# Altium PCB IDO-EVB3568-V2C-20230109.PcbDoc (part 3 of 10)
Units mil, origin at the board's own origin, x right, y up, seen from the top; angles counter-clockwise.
Board outline 5318 x 3544 mil, 2 copper layers (TOP, BOTTOM), stack 6.8 mil thick; 790 components, 626 nets, 2890 pads, 1922 vias.
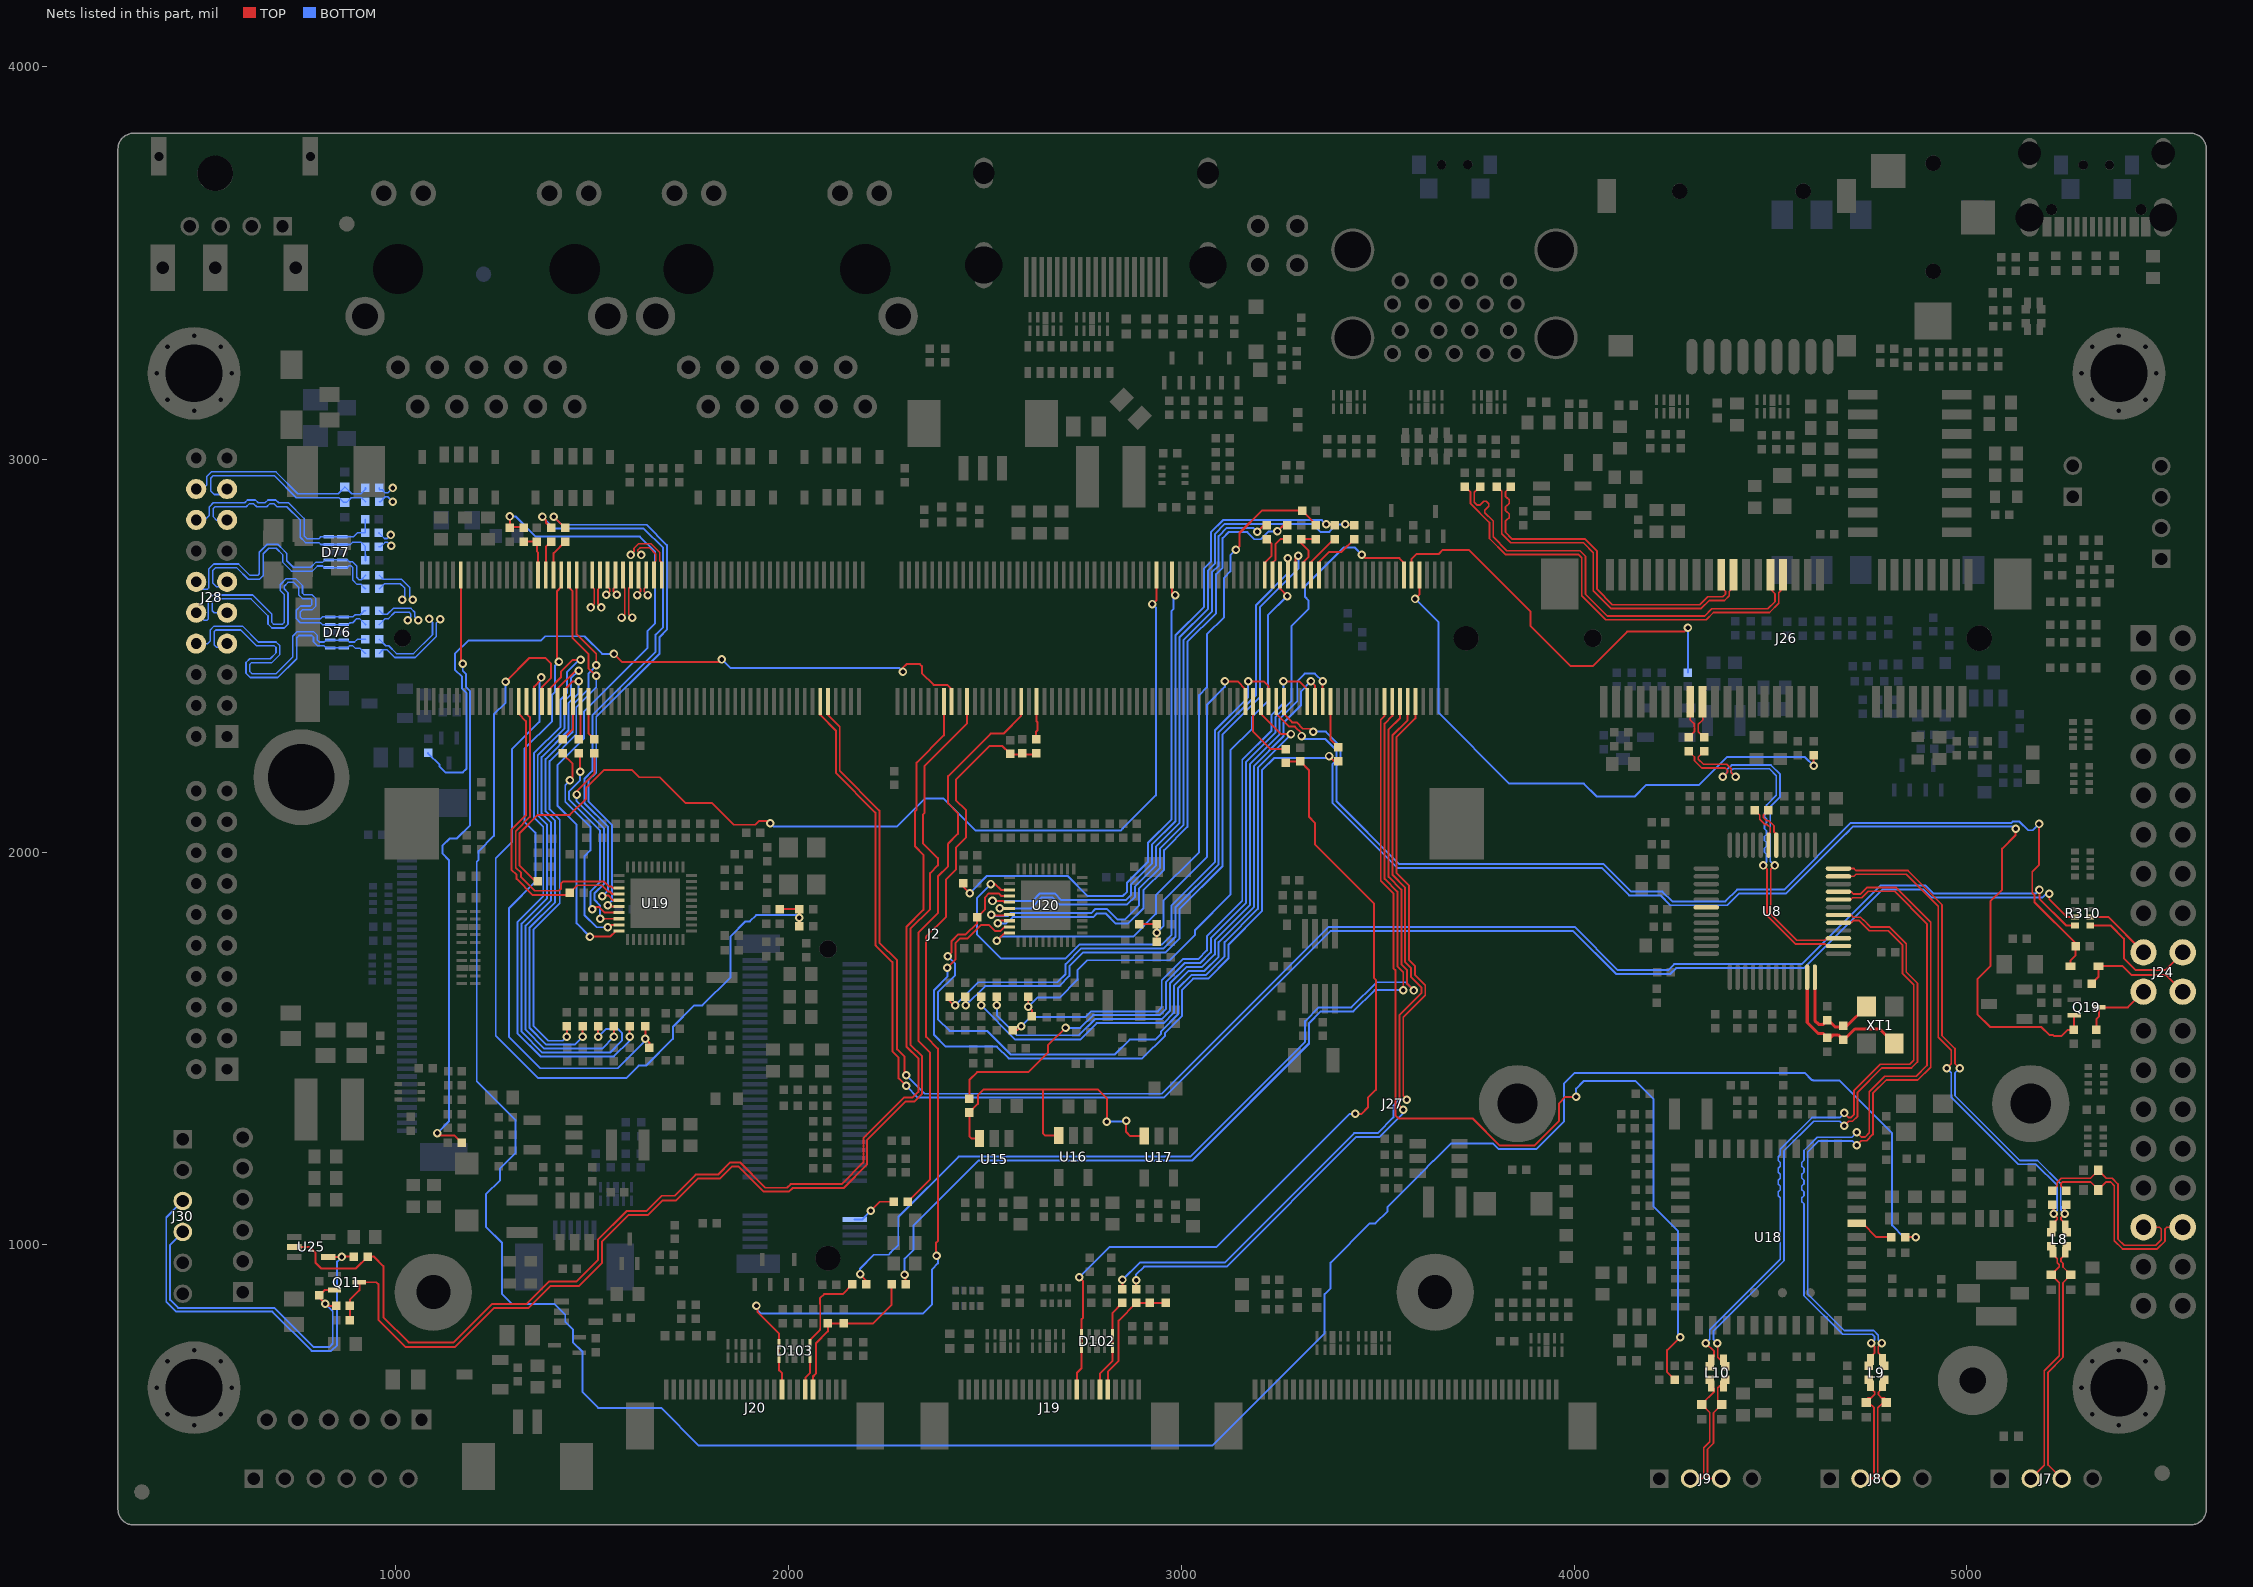
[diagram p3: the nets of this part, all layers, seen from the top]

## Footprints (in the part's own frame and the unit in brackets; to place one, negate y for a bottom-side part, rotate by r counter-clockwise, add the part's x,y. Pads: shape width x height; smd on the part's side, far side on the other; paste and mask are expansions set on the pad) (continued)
SILKSCREEN_TOP#34 [mm] "SILKSCREEN_TOP"
  rect 0.85x1.6 smd: 1(-1.25,0) 2(1.25,0)
  silkscreen extent -1.91,-1.04 1.88,1.09, body extent -1.8,-0.95 1.8,0.95, height 3.81

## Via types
v1: diameter 21.65, hole 11.81, TOP to BOTTOM, 1878 vias
v2: diameter 17.72, hole 7.87, TOP to BOTTOM, 44 vias

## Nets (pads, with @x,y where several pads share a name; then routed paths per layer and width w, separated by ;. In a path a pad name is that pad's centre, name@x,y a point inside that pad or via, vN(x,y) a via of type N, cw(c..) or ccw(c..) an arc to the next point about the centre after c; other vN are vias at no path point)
4G_PWREN_H_GPIO0_D5: J2.11 R344.1 | length 1053.2
  TOP w5: J2.11@3586.22,2706.42 3586.22,2747.22 3599,2760 3656,2760 3666,2770 3732,2770 3888.5,2613.5 3888.5,2576.5 3991,2474 4047,2474 4135,2562 4280,2562 v1(4290,2572)
  BOTTOM w5: R344.1@4290,2457.72 v1(4290,2572)
4G_RESET_L_GPIO0_D4: J2.9 R337.2 | length 1502.4
  TOP w5: v1(3595,2645) 3605.9,2655.9 J2.9@3605.9,2706.42 ; v1(4610,2220) R337.2@4610,2247.28
  BOTTOM w5: v1(3595,2645) 3595.9,2645 3655,2585.9 3655,2355 3835,2175 4025.14,2175 4058.14,2142 4154,2142 4183,2171 4318,2171 4389,2242 4588,2242 v1(4610,2220)
5G_SSRXN: J26.23 R423.2 | length 1131.6
  TOP w4.5: R423.2@3722,2931.28 3736.5,2916.78 3736.5,2887.5 3784.5,2839.5 3784.5,2799.06 3825.06,2758.5 4011.06,2758.5 4019.5,2750.06 4019.5,2653.06 4080.56,2592 4336.44,2592 4354.94,2610.5 4497.5,2610.5 4521.1,2634.1 4521.1,2661.1 4532.1,2672.1 J26.23@4532.1,2706.4
5G_SSRXP: J26.25 R422.2 | length 1135.8
  TOP w4.5: R422.2@3761,2931.28 3746,2916.28 3746,2891.44 3753.43,2884.01 3759.79,2884.01 3769.71,2893.93 3776.07,2893.93 3782.44,2887.56 3782.44,2881.2 3772.52,2871.28 3772.52,2864.92 3794,2843.44 3794,2803 3829,2768 4015,2768 4029,2754 4029,2657 4084.5,2601.5 4332.5,2601.5 4351,2620 4493.56,2620 4511.6,2638.03 4511.6,2658.4 4500.6,2669.4 J26.25@4500.6,2706.4
5G_SSTXN: C187.2 J26.31 | length 911.7
  TOP w4.5: C187.2@3803,2931.28 3815.5,2918.78 3815.5,2811.5 3839,2788 4024,2788 4049,2763 4049,2665.56 4093.56,2621 4324,2621 4344,2641 4383,2641 4395.1,2653.1 4395.1,2664.1 4406.1,2675.1 J26.31@4406.1,2706.4
5G_SSTXP: C189.2 J26.33 | length 899.7
  TOP w4.5: C189.2@3839,2931.28 3825,2917.28 3825,2906.26 3829.5,2901.76 3830.5,2901.76 3835,2897.26 3835,2888.26 3830.5,2883.76 3829.5,2883.76 3825,2879.26 3825,2870.26 3829.5,2865.76 3830.5,2865.76 3835,2861.26 3835,2852.26 3830.5,2847.76 3829.5,2847.76 3825,2843.26 3825,2815.44 3842.94,2797.5 4027.94,2797.5 4058.5,2766.94 4058.5,2669.5 4097.5,2630.5 4320.06,2630.5 4340.06,2650.5 4379.06,2650.5 4385.6,2657.03 4385.6,2664.4 4374.6,2675.4 J26.33@4374.6,2706.4
BT_REG_ON_H_GPIO1_D4: J2.18 R209.1 | length 2651.5
  TOP w5: J2.18@3517.32,2383.58 3517.32,2347.32 3507.63,2337.63 3507.63,1927.37 3540,1895 3540,1705 3545,1700 3545,1330 3553,1322 3742.14,1322 3811.14,1253 3898.72,1253 3961.83,1316.12 3961.83,1360.83 3978,1377 v1(4005,1377) ; R209.1@4256,657.28 4237,676.28 4237,732 v1(4270,765)
  BOTTOM w5: v1(4005,1377) 4005,1398 4024,1417 4157,1417 4201.67,1372.33 4201.67,1098.33 4265,1035 4265,770 v1(4270,765)
BT_WAKE_HOST: R199.2 U18.7 | length 102.5
  TOP w5: U18.7@4719.41,1055.43 4734.57,1055.43 4770,1020 R199.2@4807.28,1020
BT_WAKE_HOST_H_GPIO2_C1: J2.228 R199.1 | length 6682.9
  TOP w5: v1(1279,2434) 1340,2495 1380,2495 1395,2480 1395,2444 1371.65,2420.65 J2.228@1371.65,2383.58 ; R199.1@4842.72,1020 v1(4870,1020)
  BOTTOM w5: v1(1279,2434) 1279,2381 1249,2351 1249,2041.43 1210.5,2002.93 1210.5,1980.5 1205.67,1975.67 1205.67,1416.92 1304,1318.59 1304,1234 1265,1195 1265,1165 1229,1129 1229,1046 1270,1005 1270,875 1295,850 1402.86,850 1431,821.86 1431,804.21 1450.33,784.88 1450.33,752.1 1475,727.43 1475,625 1515,585 1675,585 1771,489 3079,489 3365,775 3365,875 3380,890 3380,955 3480,1055 3485.86,1055 3494.14,1055 3525.14,1086 3525.14,1097 3610.67,1182.53 3610.67,1183.09 3641.91,1214.32 3642.47,1214.32 3686.14,1258 3793.95,1258 3807.88,1244.07 3816.16,1244.07 ; 3816.16,1244.08 3904.07,1244.08 3974,1314 3974,1410 4002,1438 4587,1438 4605,1420 4607.86,1420 4608.86,1419 4675,1419 4810,1284 4810,1050 4840,1020 v1(4870,1020)
CAM0_PDN_H_GPIO1_D0: J2.10 R150.1 | length 2045.9
  TOP w5: R150.1@2850,887.72 v1(2850,911) ; v1(3574,1370) 3574,1371 3565,1380 3565,1580 3621,1636 3621,1661 3595,1687 3595,1710 3580,1725 3580,1915 3547.63,1947.37 3547.63,2292.63 3596.06,2341.06 J2.10@3596.06,2383.58
  BOTTOM w5: v1(2850,911) 2894,955 3110,955 3440,1285 3500,1285 3540,1325 3540,1355 3555,1370 v1(3574,1370)
CAM0_RST_L__GPIO1_D1: J2.12 R151.1 | length 2009.5
  TOP w5: R151.1@2885,887.72 v1(2885,910) ; v1(3565,1344) 3555,1354 3555,1585 3611,1641 3611,1656 3585,1682 3585,1705 3570,1720 3570,1910 3537.63,1942.37 3537.63,2297.63 3576.37,2336.37 J2.12@3576.37,2383.58
  BOTTOM w5: v1(2885,910) 2885,925 2905,945 3115,945 3445,1275 3505,1275 3565,1335 v1(3565,1344)
CAM1_PDN_H_GPIO1_D2: J2.14 R164.1 | length 2613.7
  TOP w5: v1(2182,925.88) 2182,924 2197.72,908.28 R164.1@2197.72,900 ; J2.14@3556.69,2383.58 3556.69,2341.69 3527.63,2312.63 3527.63,1937.37 3560,1905 3560,1715 3575,1700 3575,1665 v1(3592,1648)
  BOTTOM w5: v1(2182,925.88) 2182,940 2217,975 2254.25,975 2260.11,980.86 2279,999.75 2279,1071.14 2432.86,1225 2975.57,1225 3017,1225 3022,1225 3315,1518 3315,1570 3350,1605 3433,1605 3497,1669 3571,1669 v1(3592,1648)
CAM1_RST_L_GPIO1_C7: J2.16 R165.1 | length 2448.5
  TOP w5: v1(2295,924) 2297.72,921.28 R165.1@2297.72,900 ; J2.16@3537,2383.58 3537,2347 3517.63,2327.63 3517.63,1932.37 3550,1900 3550,1710 3565,1695 v1(3565,1649)
  BOTTOM w5: v1(2295,924) 2295,965 2318,988 2318,1050 2483,1215 2971.43,1215 3021.14,1215 3027,1215 3325,1513 3325,1565 3355,1595 3438,1595 3492,1649 v1(3565,1649)
CAM_CLKOUT0: J2.108 R163.1 | length 97.7
  TOP w5: R163.1@2630,2287.72 2630,2307.05 2633,2310.05 2633,2332 2631.49,2333.51 J2.108@2631.49,2383.58
CAMERA_PWREN: R416.2 U15.3 U16.3 U17.3 | length 828.4
  TOP w5: U15.3@2486.17,1271.37 2465,1271.37 2460,1276.37 R416.2@2460,1337.28 2482,1359.28 2482,1381 2497,1396 2648,1396 ; U16.3@2687.6,1278.15 2653,1278.15 2648,1283.15 2648,1396 ; v1(2810,1314) 2810,1373 2787,1396 2648,1396 ; v1(2859.37,1316.16) 2859.37,1287.63 2869.91,1277.09 U17.3@2905.32,1277.09
  BOTTOM w5: v1(2810,1314) 2857.21,1314 v1(2859.37,1316.16)
CAMERA_PWREN_GPIO4_D2: J2.13 R416.1 | length 2226.9
  TOP w5: R416.1@2460,1372.72 2460,1420 2480,1440 2610,1440 2660,1490 2660,1508 v1(2705,1553) ; v1(3459,2758) 3468,2749 3555,2749 3566.53,2737.47 J2.13@3566.53,2706.42
  BOTTOM w5: v1(2705,1553) 2743,1553 2775,1585 2945,1585 2961,1601 2961,1670 3009,1718 3048,1718 3075,1745 3075,1781 3165,1871 3165,2230 3240,2305 3240,2345 3280,2385 3280,2576 3324,2620 3324,2641 3315,2650 3315,2678 3413,2776 3441,2776 v1(3459,2758)
CAN1_RX: J24.18 R310.5 | length 330.3
  TOP w5: R310.5@5314.69,1813.5 5366.5,1813.5 5400,1780 5400,1730 5430,1700 5505,1700 J24.18@5550,1745
CAN1_RX_M0: J2.154 R310.4 | length 4402.7
  TOP w5: J2.154@2100,2383.58 2100,2350 2130,2320 2130,2207 2231,2106 2231,1770 2276,1725 2276,1498 2295,1479 2295,1436 v1(2299,1432) ; v1(5185,1904) 5185,1882.15 5253.64,1813.5 R310.4@5275.31,1813.5
  BOTTOM w5: v1(2299,1432) 2346,1385 2950,1385 3375,1810 4001.14,1810 4111.14,1700 4240,1700 4255,1715 4580,1715 4780,1915 4895,1915 4915,1895 5176,1895 v1(5185,1904)
CAN1_TX: J24.17 R310.6 | length 172.7
  TOP w5: R310.6@5314.69,1835.16 5359.84,1835.16 J24.17@5450,1745
CAN1_TX_M0: J2.156 R310.3 | length 4413.7
  TOP w5: J2.156@2080.31,2383.58 2080.31,2349.69 2120,2310 2120,2202 2221,2101 2221,1762 2222,1762 2264,1720 2264,1493 2280,1477 2280,1424 v1(2299,1405) ; v1(5210,1894) 5210,1880 5254.84,1835.16 R310.3@5275.31,1835.16
  BOTTOM w5: v1(2299,1405) 2329,1375 2955,1375 3380,1800 3997,1800 4107,1690 4245,1690 4260,1705 4585,1705 4785,1905 4890,1905 4910,1885 5193,1885 5202,1894 v1(5210,1894)
CAN2_RX: D90.C J24.20 R401.2 | length 293.8
  TOP w5: R401.2@5317.72,1665 5335.43,1682.71 D90.C@5335.43,1710 5397,1710 5420,1687 5508,1687 J24.20@5550,1645
CAN2_RX_M0: D90.A J2.44 R398.2 | length 2768.5
  TOP w5: J2.44@3261.41,2383.58 3261.41,2351.59 3282.2,2330.8 3293.2,2330.8 3309.5,2314.5 3328.5,2314.5 v1(3336,2307) ; v1(5184,2072) 5184,1967.92 5166.67,1950.59 5166.67,1896.41 5173,1890.08 5173,1872 5277.28,1767.72 R398.2@5277.28,1760 5277.28,1737.28 5264.57,1724.57 D90.A@5264.57,1710
  BOTTOM w5: v1(3336,2307) 3368,2307 3405,2270 3405,2230 3395,2220 3395,2130 3555,1970 4075,1970 4145,1900 4225,1900 4250,1875 4330.43,1875 4385,1875 4415,1905 4535,1905 4705,2075 5010.28,2075 5114.08,2075 5117.41,2078.33 5132.59,2078.33 ; 5132.6,2078.32 5133.68,2078.32 5156,2056 5168,2056 v1(5184,2072)
CAN2_TX: J24.19 Q19.3 R400.2 | length 190
  TOP w5: R400.2@5330,1547.72 5330,1575 5336.5,1581.5 Q19.3@5336.5,1605 5410,1605 J24.19@5450,1645
CAN2_TX_M0: J2.46 Q19.2 R399.2 | length 3124.4
  TOP w5: J2.46@3241.73,2383.58 3241.73,2353.27 3275,2320 3289,2320 3306,2303 v1(3306,2296) ; v1(5125,2060) 5124,2059 5124,2043 5090,2009 5090,1905 5060,1875 5060,1710 5027,1677 5027,1588 5060,1555 5190,1555 5209.99,1535.01 5218.79,1535.01 5222.13,1531.67 5240.63,1531.67 5256.67,1547.72 R399.2@5273,1547.72 5273.5,1548.22 Q19.2@5273.5,1585.32
  BOTTOM w5: v1(3306,2296) 3314,2288 3367,2288 3395,2260 3395,2235 3385,2225 3385,2125 3550,1960 4070,1960 4140,1890 4220,1890 4245,1865 4326.28,1865 4390,1865 4420,1895 4540,1895 4686.57,2041.57 4692.43,2047.43 4710,2065 5058.51,2065 5108.22,2065 5120,2065 v1(5125,2060)
CIF_CLK0: C95.2 D102.5 D102.6 J19.9 R149.2 | length 2218.5
  TOP w5: J19.9@2733.9,632.01 2733.9,673.9 2745.63,685.63 D102.6@2745.63,737.78 D102.5@2745.63,772.22 2745.63,810.63 2750,815 2750,908 v1(2740,918) ; R149.2@3266,2227.28 3270,2231.28 C95.2@3303,2231.28 3325,2209.28 3325,2090 3340,2075 3340,2020 3490,1870 3490,1680 3495,1675 3495,1395 3475,1375 3475,1350 3459,1334 v1(3443,1334)
  BOTTOM w5: v1(2740,918) 2817,995 3090,995 3429,1334 v1(3443,1334)
CIF_CLK1: C97.2 D103.5 D103.6 J20.9 R163.2 R421.2 | length 2373.4
  TOP w5: v1(1918,845) 1920,843 1920,830 1975.63,774.37 D103.5@1975.63,747.22 D103.6@1975.63,712.78 1975.63,680.37 1983.19,672.81 J20.9@1983.19,632.01 ; v1(2376.5,972.5) 2375,974 2375,1005 2380,1010 2380,1500 2350,1530 2350,1784.14 2350.81,1784.96 2350.81,1785.81 2400,1835 2400,1930 2425.95,1955.95 2425.95,1970.95 2426,1971 2426,2012 2451,2037 2451,2107.64 2426,2132.64 2426,2185.14 2511.97,2271.12 2543.16,2271.12 C97.2@2564,2250.28 2565,2249.28 2592,2249.28 R421.2@2595,2252.28 2598,2249.28 2627,2249.28 R163.2@2630,2252.28
  BOTTOM w5: v1(1918,845) 1920,843 1920,835 1930,825 2341,825 2365,849 2365,938 2380,953 2380,969 v1(2376.5,972.5)
CIF_CLKOUT_SOC: J2.52 R149.1 | length 178.1
  TOP w5: J2.52@3182.67,2383.58 3182.67,2307.33 3227.28,2262.72 R149.1@3266,2262.72
CIF_PDN0: D102.1 D102.10 J19.6 R150.2 | length 243.9
  TOP w5: J19.6@2792.95,632.01 2792.95,672.95 2824.37,704.37 D102.10@2824.37,737.78 D102.1@2824.37,772.22 2824.37,826.65 R150.2@2850,852.28
CIF_PDN1: D103.1 D103.10 J20.6 R164.2 | length 345.7
  TOP w5: J20.6@2042.24,632.01 2042.24,662.25 2054.37,674.37 D103.10@2054.37,712.78 D103.1@2054.37,747.22 2054.37,758.37 2080,784 2080,786.02 2080.33,786.35 2080.33,849.65 2080,849.98 2080,865 2090,875 2137.28,875 R164.2@2162.28,900
CIF_RST0: C96.2 J19.5 R151.2 R156.1 | length 325.2
  TOP w5: J19.5@2812.64,632.01 2812.64,677.64 2840,705 2840,807.28 R151.2@2885,852.28 C96.2@2920,852.28 R156.1@2960,852.28
CIF_RST1: C99.2 J20.5 R165.2 R166.1 | length 418.5
  TOP w5: J20.5@2061.93,632.01 2061.93,665 2069,672.07 2069,749 2100,780 C99.2@2100,800.28 R166.1@2140,800.28 2215.28,800.28 2262.28,847.28 R165.2@2262.28,900
CLK_32K_OUT: J27.68 R352.2 | length 118.1
  TOP w5: v1(2209,1087) 2232,1110 R352.2@2267.28,1110
  BOTTOM w5: J27.68@2167.91,1064.72 2186.72,1064.72 v1(2209,1087)
CLK_32K_OUT_GPIO0_B0: J2.112 R352.1 | length 1458.3
  TOP w5: R352.1@2302.72,1110 2360,1167.28 2360,1490 2330,1520 2330,1795 2380,1845 2380,1938.29 2405.95,1964.24 2405.95,1979.24 2406,1979.29 2406,2021 2406.33,2021.33 2406.33,2022.26 2431,2046.94 2431,2099.35 2406,2124.35 2406,2194 2514,2302 2547,2302 2592.12,2347.12 J2.112@2592.12,2383.58
DM1_: D18.2 J7.2 L8.3 R52.2 | length 647.8
  TOP w4.5: J7.2@5163.03,405 5197.5,439.47 5197.5,679.94 5235.5,717.94 5235.5,903.4 D18.2@5215,923.9 5235.5,944.4 5235.5,949.5 5230.25,954.75 5230.25,964.75 5219.25,975.75 L8.3@5219.25,981.53 5219.25,993.03 R52.2@5215,997.28
DM2_: D23.2 J8.2 L9.3 R64.2 | length 315.4
  TOP w4.5: J8.2@4729.33,405 4759.45,405 4763.95,409.5 4763.95,585 4750.05,598.9 D23.2@4744,598.9 4744,605.5 4748.5,610 4755.25,610 4765.56,620.31 4765.56,624.44 4754.25,635.75 L9.3@4754.25,641.53 4754.25,653.03 R64.2@4750,657.28
DM3_: D25.2 J9.2 L10.3 R75.2 | length 317.9
  TOP w4.5: J9.2@4295.63,405 4325.75,405 4330.25,409.5 4330.25,483.69 4345.5,498.94 4345.5,573.4 D25.2@4325,593.9 4325,595 4356.5,626.5 4356.5,633.44 4351,638.94 4350.05,638.94 4349.25,639.74 L10.3@4349.25,640.53 4346.74,640.53 4345,642.28 R75.2@4345,656.28
DM4: J26.36 R340.1 | length 101.5
  TOP w4.5: J26.36@4327.4,2383.6 4327.4,2336.67 4316.4,2325.67 4316.4,2307.32 R340.1@4331,2292.72
DM_1: D65.1 J24.31 R307.2 | length 545.9
  TOP w4.5: R307.2@5217,1137.72 5230.25,1150.97 5230.25,1159.94 5240.31,1170 5315,1170 5334.9,1189.9 D65.1@5334.9,1190 5354.9,1170 5369.94,1170 5385,1154.94 5385,1015 5400.5,999.5 5481.06,999.5 5495.25,1013.69 5495.25,1040.5 5490.75,1045 J24.31@5450,1045
DP1_: D20.2 J7.3 L8.4 R56.2 | length 647.5
  TOP w4.5: J7.3@5241.77,405 5207,439.77 5207,676 5245,714 5245,903.9 D20.2@5265,923.9 5245,943.9 5245,953.44 5239.75,958.69 5239.75,964.75 5250.75,975.75 L8.4@5250.75,981.53 5250.75,993.03 R56.2@5255,997.28
DP2_: D22.2 J8.3 L9.4 R67.2 | length 316.1
  TOP w4.5: R67.2@4790,657.28 4785.75,653.03 L9.4@4785.75,641.53 4785.75,635.75 4775.06,625.06 4775.06,618.69 4783.75,610 4790.5,610 4795,605.5 D22.2@4795,598.9 4787.35,598.9 4773.45,585 4773.45,409.5 4777.95,405 J8.3@4808.07,405
DP3_: D26.2 J9.3 L10.4 R78.2 | length 316.3
  TOP w4.5: J9.3@4374.37,405 4344.25,405 4339.75,409.5 4339.75,479.75 4355,495 4355,572.9 D26.2@4376,593.9 4366,603.9 4366,636 4370.53,640.53 L10.4@4380.75,640.53 4380.75,652.03 R78.2@4385,656.28
DP4: J26.38 R341.1 | length 101.6
  TOP w4.5: R341.1@4292,2292.72 4306.9,2307.62 4306.9,2325.67 4295.9,2336.67 J26.38@4295.9,2383.6
DP_1: D64.1 J24.32 R308.2 | length 546.6
  TOP w4.5: R308.2@5253,1137.72 5239.75,1150.97 5239.75,1156 5244.25,1160.5 5315,1160.5 5334.9,1140.6 D64.1@5334.9,1140 5355.4,1160.5 5366,1160.5 5375.5,1151 5375.5,1011.06 5396.56,990 5485,990 5504.75,1009.75 5504.75,1040.5 5509.25,1045 J24.32@5550,1045
DRV: U8.42
EDP_EN_H_GPIO0_C5: J2.130 R393.2 | length 1838.1
  TOP w5: v1(1555,2505) 1575,2485 1824,2485 v1(1830,2491) ; v1(2291,2460) 2291,2470 2300,2479 2334,2479 2339,2474 2339,2456 2369,2426 2404,2426 2414.96,2415.04 J2.130@2414.96,2383.58
  BOTTOM w5: R393.2@1082,2253.28 1082,2251.28 1111,2222.28 1111,2218 1125.73,2203.27 1170.27,2203.27 1179,2212 1179,2406.09 1168.67,2416.42 1168.67,2446.33 1150,2465 1150,2505 1184,2539 1369,2539 1380,2550 1480,2550 1525,2505 v1(1555,2505) ; v1(1830,2491) 1852,2469 2282,2469 v1(2291,2460)
EDP_ON_: J30.4 Q11.2 R388.2 R389.2 | length 864.6
  TOP w5: Q11.2@843.5,885.32 818.03,885.32 R388.2@805,872.28 805,865 v1(820,850) 825,845 R389.2@847.28,845
  BOTTOM w5: J30.4@457.09,1033.27 457.09,1032.09 425,1000 425,860 445,840 690,840 790,740 830,740 839,749 839,831 v1(820,850)
EDP_ON_GPIO0_C3: J2.126 Q11.3 R387.2 R389.1 | length 3152.5
  TOP w5: R387.2@882.72,808 R389.1@882.72,845 882.72,860.72 906.5,884.5 Q11.3@906.5,905 950,905 955,900 955,810 1025,740 1150,740 1250,840 1338,840 1393,895 1465,895 1525,955 1525,990.71 1525,1007.28 1525,1009 1592,1076 1633.29,1076 1641.57,1076 1679.28,1113.71 1713.71,1113.71 1769,1169 1825,1169 1856,1200 1871.86,1200 1936.19,1135.66 2000.66,1135.66 2010,1145 2140,1145 2200,1205 2200,1267.71 2297.29,1365 2320,1365 2340,1385 2340,1480 2310,1510 2310,1805 2360,1855 2360,1946.75 2379.65,1966.41 2379.65,1985.2 2341.67,2023.18 2341.67,2095.74 2346,2100.06 2346,2220.14 2454.33,2328.47 J2.126@2454.33,2383.58
EDP_PWM7: J2.132 R390.1 U25.2 | length 3253.2
  TOP w5: U25.2@740.53,995 780,995 795,980 795,955 810,940 897.72,940 R390.1@927.72,970 944,970 968,946 968,816 1032,752 1147,752 1245,850 1333,850 1390,907 1460,907 1514,961 1514,1013 1587,1086 1637.43,1086 1676.72,1125.29 1709.29,1125.29 1763,1179 1820,1179 1851,1210 1876,1210 1940.34,1145.66 1995.66,1145.66 2005,1155 2135,1155 2190,1210 2190,1271.86 2293.14,1375 2315,1375 2330,1390 2330,1475 2300,1505 2300,1810 2343,1853 2343,1993.57 2321.67,2014.9 2321.67,2104.02 2326,2108.35 2326,2228.43 2395.27,2297.7 J2.132@2395.27,2383.58
EDP_PWM7_: J30.3 R390.2 U25.4 | length 1062.2
  TOP w5: U25.4@827.14,969.41 v1(862,969.41) 862.59,970 R390.2@892.28,970
  BOTTOM w5: J30.3@457.09,1112.01 415,1069.92 415,855 440,830 685,830 785,730 835,730 850,745 850,957.41 v1(862,969.41)
EDP_TX_AUXN: C235.2 J2.197 | length 198.1
  TOP w4: v1(1598,2757) 1606,2765 1606,2774 1617.6,2785.6 1649.4,2785.6 1671.77,2763.23 1671.77,2742.23 1676.77,2737.23 J2.197@1676.77,2706.42
  BOTTOM w4: C235.2@956.72,2778 960.72,2778 971.72,2789 979,2789 v1(987.65,2780.36)
EDP_TX_AUXN_: C235.1 D77.4 D77.7 J28.15 R384.2 | length 569.7
  BOTTOM w4: J28.15@570,2846.18 568.82,2845 543.86,2845 535,2853.86 535,2875.77 539,2879.77 618.77,2879.77 626,2887 638,2887 645.22,2879.77 670.77,2879.77 678,2887 690,2887 697.22,2879.77 722.09,2879.77 756,2845.86 756,2801.86 769.33,2788.53 803.72,2788.53 808.56,2783.68 D77.4@828.78,2783.68 D77.7@863.22,2783.68 884,2783.68 889.32,2789 912,2789 921.28,2779.72 C235.1@921.28,2778 921.28,2758.17 922.28,2757.17 R384.2@922.28,2743
EDP_TX_AUXP: C236.2 J2.199 | length 167
  TOP w4: v1(1625,2757) 1616,2766 1616,2769.86 1621.74,2775.6 1645.26,2775.6 1661.77,2759.08 1661.77,2741.77 1657.08,2737.08 J2.199@1657.08,2706.42
  BOTTOM w4: C236.2@956.72,2814 956.72,2813 970.72,2799 978,2799 v1(987,2808)
EDP_TX_AUXP_: C236.1 D77.5 D77.6 J28.16 R385.1 | length 576.9
  BOTTOM w4: J28.16@491.26,2846.18 513.18,2846.18 525,2858 525,2879.91 534.86,2889.77 614.62,2889.77 621.85,2897 642.14,2897 649.37,2889.77 666.62,2889.77 673.85,2897 694.14,2897 701.37,2889.77 726.23,2889.77 766,2850 766,2806 773.48,2798.53 803.72,2798.53 808.57,2803.37 D77.5@828.78,2803.37 D77.6@863.22,2803.37 891.82,2803.37 902.45,2814 C236.1@921.28,2814 R385.1@921.28,2848
EDP_TX_D0N: C241.2 J2.213 | length 315.3
  TOP w4: J2.213@1519.29,2706.42 1519.29,2674.29 1514.45,2669.45 1514.45,2654.14 1514.44,2632 v1(1523.09,2623.35)
  BOTTOM w4: C241.2@957.72,2507 966.24,2515.52 977.34,2515.52 996.86,2496 1049,2496 1103,2550 1103,2583.71 v1(1112.65,2593.36)
EDP_TX_D0N_: C241.1 D76.1 D76.10 J28.7 | length 792.4
  BOTTOM w4: J28.7@570,2531.22 560.78,2522 543,2522 537,2528 537,2562 541,2566 604.86,2566 645.38,2525.47 690.53,2525.47 694.53,2521.47 694.53,2507.67 679.86,2493 627.86,2493 618,2483.14 618,2455.86 628.86,2445 699.14,2445 747,2492.86 747,2546 752.86,2551.86 786,2551.86 790,2547.86 790,2536 800.53,2525.47 817.53,2525.47 822.37,2520.63 D76.1@832.78,2520.63 D76.10@867.22,2520.63 876.63,2520.63 881.47,2525.47 890.38,2525.47 896.86,2519 909,2519 921,2507 C241.1@922.28,2507
EDP_TX_D0P: C242.2 J2.215 | length 302
  TOP w4: v1(1495.8,2623.35) 1504.44,2632 1504.44,2658.28 1504.45,2670.55 1499.6,2675.4 J2.215@1499.6,2706.42
  BOTTOM w4: C242.2@957.72,2542 974.2,2525.52 981.49,2525.52 1001,2506 1044.86,2506 1093,2554.14 1093,2586 v1(1085,2594)
EDP_TX_D0P_: C242.1 D76.2 D76.9 J28.8 | length 793.3
  BOTTOM w4: J28.8@491.26,2531.22 520.22,2531.22 527,2538 527,2566.14 536.86,2576 609,2576 649.53,2535.47 694.67,2535.47 704.53,2525.62 704.53,2503.53 684,2483 632,2483 628,2479 628,2460 633,2455 695,2455 737,2497 737,2550.14 748.71,2561.86 790.14,2561.86 800,2552 800,2540.14 804.67,2535.47 817.47,2535.47 822.32,2540.32 D76.2@832.78,2540.32 D76.9@867.22,2540.32 876.68,2540.32 881.53,2535.47 894.52,2535.47 901.05,2542 C242.1@922.28,2542
EDP_TX_D1N: C239.2 J2.209 | length 170.7
  TOP w4: J2.209@1558.66,2706.42 1558.66,2676.66 1553.82,2671.82 1553.82,2664 v1(1562.46,2655.36)
  BOTTOM w4: C239.2@957.72,2580 972.72,2595 981,2595 997,2611 1034,2611 1038,2607 1038,2599 v1(1030,2591)
EDP_TX_D1N_: C239.1 D76.4 D76.7 J28.9 | length 784.3
  BOTTOM w4: J28.9@570,2609.96 537.04,2609.96 532,2615 532,2638 539,2645 630.86,2645 674,2601.86 674,2581 684,2571 715.14,2571 725,2580.86 725,2661 715.14,2670.86 715.14,2677.14 725,2687 739.86,2687 752,2674.86 752,2655.86 761.86,2646 782,2646 786,2642 786,2631.14 781.86,2627 757,2627 746,2616 746,2595 756.48,2584.53 807.72,2584.53 812.56,2579.68 D76.4@832.78,2579.68 D76.7@867.22,2579.68 878.68,2579.68 883.52,2584.53 889.67,2584.53 900.14,2595 907.28,2595 C239.1@922.28,2580
EDP_TX_D1P: C240.2 J2.211 | length 184.8
  TOP w4: v1(1535.17,2655.36) 1543.82,2664 1543.82,2671.18 1538.97,2676.03 J2.211@1538.97,2706.42
  BOTTOM w4: C240.2@957.72,2615 966.65,2606.07 977.93,2606.07 992.86,2621 1038.14,2621 1048,2611.14 1048,2600 v1(1057,2591)
EDP_TX_D1P_: C240.1 D76.5 D76.6 J28.10 | length 815.4
  BOTTOM w4: J28.10@491.26,2609.96 510.05,2591.17 519.17,2591.17 522,2594 522,2642.14 534.86,2655 635,2655 684,2606 684,2585.14 688.14,2581 711,2581 715,2585 715,2656.86 705.14,2666.71 705.14,2681.29 720.86,2697 744,2697 762,2679 762,2660 766,2656 786.14,2656 796,2646.14 796,2627 786,2617 761.14,2617 756,2611.86 756,2599.14 760.62,2594.53 807.72,2594.53 812.57,2599.37 D76.5@832.78,2599.37 D76.6@867.22,2599.37 890.37,2599.37 896,2605 909,2605 919,2615 C240.1@922.28,2615
EDP_TX_D2N: C237.2 J2.205 | length 221.3
  TOP w4: J2.205@1598.03,2706.42 1598.03,2677.03 1593,2672 1593,2606.29 v1(1601.65,2597.64)
  BOTTOM w4: C237.2@957.72,2671 970.72,2684 1011,2684 1022,2673 1022,2652 1015.76,2645.76 v1(1015.76,2643)
EDP_TX_D2N_: C237.1 D77.1 D77.10 J28.11 | length 633.5
  BOTTOM w4: J28.11@570,2688.7 557.47,2676.17 542.83,2676.17 533,2686 533,2717 540,2724 595,2724 624,2695 652.14,2695 662,2704.86 662,2759.86 676.14,2774 694.86,2774 712,2756.86 712,2738 734,2716 787.14,2716 800.14,2729 813,2729 817.37,2724.63 D77.1@828.78,2724.63 D77.10@863.22,2724.63 875.63,2724.63 880.47,2729.47 885.38,2729.47 890,2724.86 890,2693 901,2682 911,2682 922,2671 C237.1@922.28,2671
EDP_TX_D2P: C238.2 J2.207 | length 238.8
  TOP w4: v1(1574.36,2597.64) 1583,2606.28 1583,2672 1578.34,2676.66 J2.207@1578.34,2706.42
  BOTTOM w4: C238.2@957.72,2705 967.72,2695 1014.14,2695 1035,2674.14 1035,2651.05 v1(1043.05,2643)
EDP_TX_D2P_: C238.1 D77.2 D77.9 J28.12 | length 655.3
  BOTTOM w4: J28.12@491.26,2688.7 509.79,2670.17 520.17,2670.17 523,2673 523,2721.14 535.86,2734 599.14,2734 628.14,2705 648,2705 652,2709 652,2764 672,2784 690.71,2784 699,2784 716.14,2766.86 722,2761 722,2742.14 738.14,2726 783,2726 796,2739 814.01,2739 819.33,2744.32 D77.2@828.78,2744.32 D77.9@863.22,2744.32 876.68,2744.32 881.53,2739.47 889.53,2739.47 900,2729 900,2700 906,2694 911.28,2694 C238.1@922.28,2705
EDP_TX_D3N: C233.2 J2.201 | length 102.1
  TOP w4: J2.201@1637.4,2706.42 1637.4,2676.4 1632.56,2671.56 1632.56,2663.65 v1(1641.2,2655)
  BOTTOM w4: C233.2@957.72,2893 958.72,2892 959.72,2892 972.72,2905 979.09,2905 v1(991.74,2892.36)
EDP_TX_D3N_: C233.1 D80.1 J28.17 | length 517.9
  BOTTOM w4: J28.17@570,2924.92 556.08,2911 537,2911 528,2920 528,2952.51 534,2958.51 690.35,2958.51 745.86,2903 855,2903 867.1,2890.9 D80.1@870,2890.9 873.9,2890.9 886,2903 912.28,2903 C233.1@922.28,2893
EDP_TX_D3P: C234.2 J2.203 | length 104
  TOP w4: v1(1613.91,2655) 1622.56,2663.64 1622.56,2671.44 1617.71,2676.29 J2.203@1617.71,2706.42
  BOTTOM w4: C234.2@957.72,2928 957.72,2924 958.72,2923 964.72,2923 972.72,2915 979.09,2915 v1(991.74,2927.65)
EDP_TX_D3P_: C234.1 D79.1 J28.18 | length 507.2
  BOTTOM w4: J28.18@491.26,2924.92 491.34,2925 508,2925 518,2935 518,2956.66 529.86,2968.51 694.49,2968.51 750,2913 853,2913 870,2930 D79.1@870,2930.1 887.1,2913 910.71,2913 922.28,2924.57 C234.1@922.28,2928
EXT_EN: J2.249 R13.1 | length 1563.9
  TOP w5: v1(1105,1285) 1111,1279 1148.72,1279 R13.1@1167.72,1260 ; J2.249@1164.96,2706.42 1164.96,2486.04 1170,2481 v1(1170,2480)
  BOTTOM w5: v1(1105,1285) 1135,1315 1135,1933.29 1135,1980 1118,1997 1118,2016 1137,2035 1155,2035 1189,2069 1189,2410.24 1178.67,2420.57 1178.67,2445.42 1178.67,2453.33 1170,2462 v1(1170,2480)
FE1_1_DM0: R71.1 U8.30 | length 111.2
  TOP w4.5: R71.1@4495,2107.28 4482,2094.28 4482,2088.44 4490.44,2080 4496,2080 4509,2067 4509,2051.8 4514.8,2046 U8.30@4514.8,2018.3
FE1_1_DM1: L8.2 R52.1 R307.1 U8.23 | length 1320.2
  TOP w4.5: U8.23@4673.3,1938.6 4712.73,1938.6 4717.83,1943.7 4846.3,1943.7 4927.5,1862.5 4927.5,1529.06 4960.5,1496.07 4960.5,1461.68 v1(4948.82,1450) ; R52.1@5215,1032.72 5219.25,1036.97 L8.2@5219.25,1048.46 5219.25,1054.25 5230.25,1065.25 5230.25,1070 5230,1070 v1(5221,1079) 5221,1098.28 R307.1@5217,1102.28
  BOTTOM w4.5: v1(4948.82,1450) 4960.5,1438.32 4960.5,1376.07 5131.06,1205.5 5176.06,1205.5 5230,1151.56 5230,1094.86 5230.25,1094.61 5230.25,1088.25 v1(5221,1079)
FE1_1_DM2: L9.2 R64.1 U8.20 | length 1800.6
  TOP w4.5: U8.20@4673.3,1879.5 4704.5,1879.5 4709,1884 4732.44,1884 4748.94,1900.5 4816.06,1900.5 4898.5,1818.06 4898.5,1456.94 4871.06,1429.5 4791.06,1429.5 4751.5,1389.94 4751.5,1285.5 4741,1275 4731.68,1275 v1(4720,1286.68) ; R64.1@4750,692.72 4754.25,696.97 L9.2@4754.25,708.47 4754.25,714.25 4765.25,725.25 4765.25,741.5 v1(4756.57,750.18)
  BOTTOM w4.5: v1(4720,1286.68) 4707.82,1274.5 4619.5,1274.5 4585.5,1240.5 4585.5,1215.5 4580,1210 4580,1200.5 4585.5,1195 4585.5,1185.5 4580,1180 4580,1170.5 4585.5,1165 4585.5,1155.5 4580,1150 4580,1140.5 4585.5,1135 4585.5,1125.5 4580,1120 4580,1110.5 4585.5,1105 4585.5,871.06 4683.83,772.73 4758.83,772.73 4765.25,766.32 4765.25,758.87 v1(4756.57,750.18)
FE1_1_DM3: L10.2 R75.1 U8.17 | length 1635.9
  TOP w4.5: v1(4335.57,750) 4356.5,729.07 4356.5,716.8 4349.25,709.55 L10.2@4349.25,707.47 4349.25,695.97 R75.1@4345,691.72 ; U8.17@4673.3,1820.5 4705.5,1820.5 4711,1826 4725.7,1826 4751.7,1800 4800,1800 4836.5,1763.5 4836.5,1691 4865,1662.5 4865,1470 4855,1460 4780,1460 4712.5,1392.5 4712.5,1331.94 4704.96,1324.39 4699.39,1324.39 v1(4687.71,1336.08)
  BOTTOM w4.5: v1(4335.57,750) 4345.25,759.68 4345.25,783.69 4525,963.44 4525,1120 4520,1125 4520,1135 4525,1140 4525,1150 4520,1155 4520,1165 4525,1170 4525,1180 4520,1185 4520,1195 4525,1200 4525,1210 4520,1215 4520,1225 4525,1230 4525,1243.43 4605.96,1324.39 4676.03,1324.39 v1(4687.71,1336.08)
FE1_1_DM4: R340.2 U8.14 | length 895.4
  TOP w4.5: R340.2@4331,2257.28 4316.25,2242.53 4316.25,2237.19 4329.44,2224 4389,2224 4400.07,2212.93 4400.07,2202.93 v1(4411.18,2191.82) ; v1(4481.82,1966.31) 4491.5,1956.63 4491.5,1838.5 4563.5,1766.5 4638.5,1766.5 4643.6,1761.4 U8.14@4673.3,1761.4
  BOTTOM w4.5: v1(4411.18,2191.82) 4399.5,2203.5 4399.5,2207 4405,2212.5 4497.5,2212.5 4515,2195 4515,2145 4490,2120 4490,2105 4485,2100 4485,2090 4490,2085 4490,2075 4485,2070 4485,2060 4490,2055 4490,2045 4485,2040 4485,2030 4490,2025 4490,2015 4485,2010 4485,2000 4490,1995 4490,1974.49 v1(4481.82,1966.31)
FE1_1_DP0: R69.1 U8.31 | length 110.4
  TOP w4.5: R69.1@4460,2107.28 4472.5,2094.78 4472.5,2084.5 4486.5,2070.5 4492.06,2070.5 4499.5,2063.06 4499.5,2051.25 4495.2,2046.95 U8.31@4495.2,2018.3
FE1_1_DP1: L8.1 R56.1 R308.1 U8.24 | length 1335.8
  TOP w4.5: U8.24@4673.3,1958.3 4712.73,1958.3 4717.83,1953.2 4850.24,1953.2 4937,1866.44 4937,1533 4970,1500 4970,1461.68 v1(4981.68,1450) ; R308.1@5253,1102.28 5249,1098.28 v1(5249,1079) 5239.75,1069.75 5239.75,1065.25 5250.75,1054.25 L8.1@5250.75,1048.46 5250.75,1036.97 R56.1@5255,1032.72
  BOTTOM w4.5: v1(4981.68,1450) 4970,1438.32 4970,1380 5135,1215 5180,1215 5239.5,1155.5 5239.5,1098.8 5239.75,1098.55 5239.75,1088.25 v1(5249,1079)
FE1_1_DP2: L9.1 R67.1 U8.21 | length 1798.2
  TOP w4.5: U8.21@4673.3,1899.2 4705.8,1899.2 4711.5,1893.5 4728.5,1893.5 4745,1910 4820,1910 4908,1822 4908,1453 4875,1420 4795,1420 4761,1386 4761,1281.56 4744.94,1265.5 4731.68,1265.5 v1(4720,1253.82) ; v1(4783.43,750.18) 4774.75,741.5 4774.75,725.25 4785.75,714.25 L9.1@4785.75,708.47 4785.75,696.97 R67.1@4790,692.72
  BOTTOM w4.5: v1(4720,1253.82) 4708.82,1265 4623.44,1265 4595,1236.56 4595,875 4687.77,782.23 4762.77,782.23 4774.75,770.25 4774.75,758.87 v1(4783.43,750.18)
FE1_1_DP3: L10.1 R78.1 U8.18 | length 1634.6
  TOP w4.5: v1(4364.43,750) 4366,748.43 4366,714 4372.54,707.47 L10.1@4380.75,707.47 4380.75,695.97 R78.1@4385,691.72 ; U8.18@4673.3,1840.2 4705.36,1840.2 4711.06,1834.5 4729.22,1834.5 4736.15,1827.57 4737.56,1827.57 4755.63,1809.5 4803.94,1809.5 4846,1767.44 4846,1694.94 4874.5,1666.44 4874.5,1466.06 4858.94,1450.5 4783.94,1450.5 4722,1388.56 4722,1328 4708.89,1314.89 4699.39,1314.89 v1(4687.71,1303.21)
  BOTTOM w4.5: v1(4364.43,750) 4354.75,759.68 4354.75,779.75 4534.5,959.5 4534.5,1239.5 4609.89,1314.89 4676.02,1314.89 v1(4687.71,1303.21)
FE1_1_DP4: R341.2 U8.15 | length 896.3
  TOP w4.5: R341.2@4292,2257.28 4306.75,2242.53 4306.75,2233.25 4325.5,2214.5 4385.06,2214.5 4390.57,2209 4390.57,2204.07 v1(4378.32,2191.82) ; v1(4510.68,1966.31) 4501,1956.63 4501,1842.44 4567.44,1776 4638,1776 4643.1,1781.1 U8.15@4673.3,1781.1
  BOTTOM w4.5: v1(4378.32,2191.82) 4390,2203.5 4390,2210.94 4401.06,2222 4501.44,2222 4524.5,2198.94 4524.5,2141.06 4499.5,2116.06 4499.5,1977.5 v1(4510.68,1966.31)
FE1_1_XIN: C49.2 R68.1 U8.12 XT1.1 | length 278.9
  TOP w8: U8.12@4613.3,1681.7 4613.3,1571.29 4623,1561.59 4634.31,1561.59 C49.2@4645,1572.28 4647.72,1572.28 4665,1555 4682.28,1555 R68.1@4685,1557.72 4695.04,1557.72 XT1.1@4744.57,1607.24
FE1_1_XOUT: C51.2 R68.2 U8.11 XT1.3 | length 388.3
  TOP w8: U8.11@4593.6,1681.7 4593.6,1566.4 4621.19,1538.81 4633.91,1538.81 C51.2@4645,1527.72 4652.72,1527.72 4660,1535 4672.28,1535 R68.2@4685,1522.28 4687.28,1522.28 4715,1550 4778.19,1550 XT1.3@4815.43,1512.76
GMAC0_MCLKINOUT: C131.2 J2.230 R216.1 R219.2 | length 2192.8
  TOP w5: J2.230@1351.96,2383.58 1351.96,2421.96 1370,2440 v1(1370,2445) ; R216.1@1977.72,1855 R219.2@2027.28,1855 v1(2027.28,1833) C131.2@2027.28,1812
  BOTTOM w5: v1(1370,2445) 1365,2440 1365,2332 1296,2263 1296,2039.29 1296,2027 1254,1985 1254,1533.14 1266.58,1520.57 1266.58,1520.42 1362,1425 1586.36,1425 1618.03,1456.67 1636.67,1456.67 1705,1525 1705,1555 1760,1610 1780,1610 1852,1682 1852,1786 1890,1824 1901,1824 1917,1840 2020.28,1840 v1(2027.28,1833)
GMAC0_MDC: J2.232 U19.13 | length 758.9
  TOP w5: J2.232@1332.28,2383.58 1332.28,2352.72 1341,2344 1341,2089.86 1305,2053.86 1305,1961 1318.5,1947.5 1318.5,1936.5 1353,1902 1415,1902 1420,1907 1420,1920 1426,1926 1529,1926 1542,1913 1548.37,1913 1552,1909.37 U19.13@1567.48,1909.37
GMAC0_MDIO: J2.234 R249.1 U19.14 | length 777
  TOP w5: J2.234@1312.59,2383.58 1312.59,2352.41 1331,2334 1331,2094 1294,2057 1294,1955.92 1307,1942.92 1307,1932 1348,1891 1436.28,1891 R249.1@1442.28,1897 1461.28,1916 1524,1916 1540,1900 1545,1900 1551.38,1893.62 U19.14@1567.48,1893.62
GMAC0_RSTN_GPIO2_D5: J2.77 R248.1 | length 2587.7
  TOP w5: R248.1@1361.28,1926 1355,1926 1315,1966 1315,2049 1361,2095 1443,2095 1483.5,2135.5 1483.5,2163.5 1530,2210 1600,2210 1619,2191 1672,2191 1738,2125 1805,2125 1860,2070 1915,2070 1924,2079 1948,2079 v1(1953,2074) ; v1(2926,2632) 2928,2634 2929,2634 2936.61,2641.61 J2.77@2936.61,2706.42
  BOTTOM w5: v1(1953,2074) 1961,2066 1972.78,2066 1973.78,2065 2275.71,2065 2347.71,2137 2394,2137 2476,2055 2845.14,2055 2851,2060.86 2935,2144.86 2935,2623 v1(2926,2632)
GMAC0_RXCLK: C147.2 J2.223 R256.2 | length 1732.2
  TOP w5: v1(1415,2485) 1410,2490 1410,2665 1420.86,2675.86 J2.223@1420.86,2706.42 ; R256.2@1635,1557.28 v1(1635,1525) 1645,1515 C147.2@1645,1502.72
  BOTTOM w5: v1(1415,2485) 1405,2475 1405,2409.14 1397.5,2401.64 1397.5,2333.5 1327,2263 1327,2078 1355,2050 1355,1925 1288,1858 1288,1529 1367,1450 1565,1450 1635,1520 v1(1635,1525)
GMAC0_RXD0: J2.222 R252.2 | length 1321.8
  TOP w5: J2.222@1430.7,2383.58 1430.7,2415.7 1450,2435 v1(1465,2435) ; v1(1555,1530) R252.2@1555,1557.28
  BOTTOM w5: v1(1465,2435) 1465,2405 1439,2379 1439,2310 1371,2242 1371,2099 1395,2075 1395,1878 1330,1813 1330,1548 1378,1500 1525,1500 v1(1555,1530)
GMAC0_RXD1: J2.224 R253.2 | length 1514.9
  TOP w5: J2.224@1411.02,2383.58 1411.02,2416.02 1457.5,2462.5 v1(1465.5,2462.5) ; v1(1515,1530) R253.2@1515,1557.28
  BOTTOM w5: v1(1465.5,2462.5) 1445.5,2442.5 1445.5,2400.5 1429,2384 1429,2315 1361,2247 1361,2094 1385,2070 1385,1883 1320,1818 1320,1543 1373,1490 1545,1490 1575,1520 1575,1540 1565,1550 1535,1550 v1(1515,1530)
GMAC0_RXD2: J2.219 R254.2 | length 1452.7
  TOP w5: J2.219@1460.23,2706.42 1460.23,2554.77 1510,2505 v1(1510,2476) ; v1(1475,1530) R254.2@1475,1557.28
  BOTTOM w5: v1(1475,1530) 1455,1510 1383,1510 1340,1553 1340,1808 1405,1873 1405,2080 1381,2104 1381,2237 1449,2305 1449,2374 1490,2415 1490,2455 1510,2475 v1(1510,2476)
GMAC0_RXD3: J2.221 R255.2 | length 1397.2
  TOP w5: v1(1435,1530) R255.2@1435,1557.28 ; J2.221@1440.55,2706.42 1440.55,2674.45 1450,2665 1450,2545 1490,2505 1490,2469 v1(1510,2449)
  BOTTOM w5: v1(1435,1530) 1425,1520 1388,1520 1350,1558 1350,1803 1417,1870 1417,2083 1391,2109 1391,2232 1459,2300 1459,2369 1510,2420 v1(1510,2449)
GMAC0_RXDV_CRS: J2.226 R257.2 | length 1553.5
  TOP w5: J2.226@1391.33,2383.58 1391.33,2416.33 1420,2445 1420,2460 1450,2490 v1(1470,2490) ; v1(1595,1530) R257.2@1595,1557.28
  BOTTOM w5: v1(1470,2490) 1467,2490 1435,2458 1435,2405 1419,2389 1419,2320 1351,2252 1351,2089 1375,2065 1375,1888 1310,1823 1310,1538 1368,1480 1555,1480 1595,1520 v1(1595,1530)
GMAC0_TXCLK: C134.2 J2.229 R234.1 | length 120
  TOP w5: R234.1@1325,2791.28 C134.2@1359,2791.28 1359,2766 1361.81,2763.19 J2.229@1361.81,2706.42
GMAC0_TXCLK_: C135.2 R234.2 U19.20 | length 1668.2
  TOP w5: v1(1290,2855) C135.2@1290,2826.72 1291,2827.72 1324,2827.72 R234.2@1325,2826.72 ; v1(1494,1785) 1545,1785 1559.13,1799.13 U19.20@1567.48,1799.13
  BOTTOM w5: v1(1290,2855) 1305,2855 1356,2804 1621,2804 1660,2765 1660,2583 1641,2564 1641,2521 1479,2359 1479,2290 1411,2222 1411,2119 1460,2070 1460,1819 v1(1494,1785)
GMAC0_TXD0: J2.216 R224.1 | length 102.2
  TOP w5: J2.216@1489.76,2383.58 1489.76,2302.96 R224.1@1505,2287.72
GMAC0_TXD0_: R224.2 U19.18 | length 532.9
  TOP w5: v1(1460,2147) 1460,2155 1505,2200 R224.2@1505,2252.28 ; v1(1520,1830.63) U19.18@1567.48,1830.63
  BOTTOM w5: v1(1460,2147) 1460,2130 1530,2060 1530,1920 1505.5,1895.5 1505.5,1878.5 1520,1864 v1(1520,1830.63)
GMAC0_TXD1: J2.218 R227.1 | length 98
  TOP w5: R227.1@1465,2287.72 1470.07,2292.79 J2.218@1470.07,2383.58
GMAC0_TXD1_: R227.2 U19.17 | length 530.9
  TOP w5: R227.2@1465,2252.28 1469,2248.28 v1(1469,2205) ; v1(1500,1855) 1505,1860 1518,1860 1531.62,1846.38 U19.17@1567.48,1846.38
  BOTTOM w5: v1(1469,2205) 1469,2183 1441,2155 1441,2134 1520,2055 1520,1925 1495,1900 1495,1860 v1(1500,1855)
GMAC0_TXD2: J2.225 R228.1 | length 97.2
  TOP w5: J2.225@1401.18,2706.42 1401.18,2761.46 R228.1@1431,2791.28
GMAC0_TXD2_: R228.2 U19.16 | length 1417
  TOP w5: v1(1402,2854) 1429.28,2826.72 R228.2@1431,2826.72 ; v1(1539,1865) 1541,1865 1543.87,1862.13 U19.16@1567.48,1862.13
  BOTTOM w5: v1(1402,2854) 1422,2834 1638,2834 1690,2782 1690,2567 1671,2548 1671,2506 1510,2345 1510,2202.86 1490,2182.86 1490,2130 1550,2070 1550,1876 v1(1539,1865)
GMAC0_TXD3: J2.227 R231.1 | length 90.5
  TOP w5: J2.227@1381.49,2706.42 1381.49,2777.77 R231.1@1395,2791.28
GMAC0_TXD3_: R231.2 U19.15 | length 1425.3
  TOP w5: v1(1373,2854) 1382,2845 1382,2839.72 R231.2@1395,2826.72 ; v1(1525,1888) 1527,1890 1540,1890 1552.13,1877.87 U19.15@1567.48,1877.87
  BOTTOM w5: v1(1373,2854) 1403,2824 1630.85,2824 1680,2774.85 1680,2573 1661,2554 1661,2510.14 1500,2349.14 1500,2207 1480,2187 1480,2125 1540,2065 1540,1903 v1(1525,1888)
GMAC0_TXEN: J2.220 R232.1 | length 106.4
  TOP w5: R232.1@1425,2287.72 1450.39,2313.11 J2.220@1450.39,2383.58
GMAC0_TXEN_: R232.2 U19.19 | length 566
  TOP w5: R232.2@1425,2252.28 1425,2250 1450,2225 1450,2190 v1(1443,2183) ; v1(1539,1809) 1544.88,1814.88 U19.19@1567.48,1814.88
  BOTTOM w5: v1(1443,2183) 1431,2171 1431,2129 1495,2065 1495,2005 1480,1990 1480,1840 1511,1809 v1(1539,1809)
GMAC1_MCLKINOUT_M1: C155.2 J2.54 R270.1 R271.2 | length 893.2
  TOP w5: R270.1@2892.72,1817 C155.2@2937.28,1817 v1(2937.28,1795) R271.2@2937.28,1772 ; v1(3111,2435) 3143,2435 3162.99,2415.01 J2.54@3162.99,2383.58
  BOTTOM w5: v1(2937.28,1795) 2955,1812.72 2955,1877.79 3065,1987.79 3065,2375 3111,2421 v1(3111,2435)
GMAC1_MDC_M1: J2.48 U20.13 | length 1563.9
  TOP w5: v1(2515,1919) 2526,1919 2540.63,1904.37 U20.13@2562.48,1904.37 ; v1(3170,2435) 3210,2435 3222.04,2422.96 J2.48@3222.04,2383.58
  BOTTOM w5: v1(2515,1919) 2480,1884 2480,1790 2540,1730 2705,1730 2740,1765 2950,1765 2975,1790 2975,1865 3085,1975 3085,2310 3170,2395 v1(3170,2435)
GMAC1_MDIO_M1: J2.50 R297.1 U20.14 | length 2133.5
  TOP w5: v1(2405,1735) 2415,1745 2415,1774 2431,1790 2450,1790 2479.72,1819.72 R297.1@2479.72,1835 2500,1855.28 2500,1885 2510,1895 2535,1895 2541.38,1888.62 U20.14@2562.48,1888.62 ; J2.50@3202.36,2383.58 3202.36,2352.64 3254,2301 v1(3279,2301)
  BOTTOM w5: v1(2405,1735) 2423,1717 2423,1686 2380,1643 2380,1575 2410,1545 2505,1545 2565,1485 2830,1485 2868,1523 2933.92,1523 2948.33,1537.41 2948.33,1544.18 2991,1586.86 2991,1653 3026,1688 3063,1688 3110,1735 3110,1771 3195,1856 3195,2215 3279,2299 v1(3279,2301)
GMAC1_RSTN_GPIO2_D7: J2.73 R296.1 | length 1339.7
  TOP w5: R296.1@2444.28,1921 2444.28,1912.72 v1(2461,1896) ; J2.73@2975.98,2706.42 2975.98,2660 2980.98,2655 v1(2983.98,2655)
  BOTTOM w5: v1(2461,1896) 2505,1940 2710,1940 2762,1888 2850,1888 2862,1900 2862,1923 2915,1976 2915,2024 2975,2084 2975,2615 2979.98,2619.98 2979.98,2651 v1(2983.98,2655)
GMAC1_RXCLK_M1: C171.2 J2.45 R304.2 | length 1589.7
  TOP w5: R304.2@2610,1632.28 v1(2610,1607) 2619,1598 C171.2@2619,1582.72 ; J2.45@3251.57,2706.42 3251.57,2670.43 v1(3269.5,2652.5)
  BOTTOM w5: v1(2610,1607) 2633,1630 2690,1630 2735,1675 2735,1700 2760,1725 2970,1725 3035,1790 3035,1802 3125,1892 3125,2260 3180,2315 3180,2345 3220,2385 3220,2603 v1(3269.5,2652.5)
GMAC1_RXD0_M1: J2.34 R300.2 | length 1665.3
  TOP w5: v1(2530,1610) R300.2@2530,1632.28 ; J2.34@3359.84,2383.58 3359.84,2434.84 v1(3360,2435)
  BOTTOM w5: v1(2530,1610) 2530,1585 2581,1534 2739,1534 2780,1575 2950,1575 2971,1596 2971,1665.86 3013.14,1708 3053,1708 3085,1740 3085,1776 3175,1866 3175,2225 3250,2300 3250,2340 3295,2385 3295,2436 3314,2455 3340,2455 v1(3360,2435)
GMAC1_RXD1_M1: J2.36 R301.2 | length 1645.1
  TOP w5: v1(2490,1610) R301.2@2490,1632.28 ; v1(3330,2435) 3340.15,2424.85 J2.36@3340.15,2383.58
  BOTTOM w5: v1(2490,1610) 2577.07,1522.93 2742.07,1522.93 2784.14,1565 2955,1565 2981,1591 2981,1660 3019,1698 3058.86,1698 3095,1734.14 3095,1771 3185,1861 3185,2220 3260,2295 3260,2330 3305,2375 3305,2410 v1(3330,2435)
GMAC1_RXD2_M1: J2.41 R302.2 | length 1805
  TOP w5: R302.2@2450,1632.28 2451,1631.28 v1(2451,1610) ; J2.41@3290.94,2706.42 3290.94,2750 3295.94,2755 v1(3298,2755)
  BOTTOM w5: v1(2451,1610) 2500,1659 2689,1659 2715,1685 2715,1710 2750,1745 2960,1745 2995,1780 2995,1855 3105,1965 3105,2300 3200,2395 3200,2624 3298,2722 v1(3298,2755)
GMAC1_RXD3_M1: J2.43 R303.2 | length 1802.7
  TOP w5: R303.2@2410,1632.28 2410,1621 2421,1610 v1(2424,1610) ; J2.43@3271.26,2706.42 v1(3271.26,2748.81)
  BOTTOM w5: v1(2424,1610) 2483,1669 2684,1669 2705,1690 2705,1715 2745,1755 2955,1755 2985,1785 2985,1860 3095,1970 3095,2305 3190,2400 3190,2629 3271.26,2710.26 v1(3271.26,2748.81)
GMAC1_RXDV_CRS_M1: J2.38 R305.2 | length 1485.1
  TOP w5: R305.2@2570,1547.28 2582.56,1547.28 v1(2592.28,1557) ; v1(3260,2435) 3300,2435 3320.47,2414.53 J2.38@3320.47,2383.58
  BOTTOM w5: v1(2592.28,1557) 2615.28,1580 2755,1580 2770,1595 2940,1595 2950,1605 2950,1674 3004,1728 3043,1728 3065,1750 3065,1786 3155,1876 3155,2235 3230,2310 3230,2350 3260,2380 v1(3260,2435)
GMAC1_TXCLK_M1: C158.2 J2.39 R282.1 | length 141.3
  TOP w5: J2.39@3310.63,2706.42 3310.63,2738.63 3324,2752 3324,2768 3305,2787 C158.2@3305,2797.28 R282.1@3342,2797.28
GMAC1_TXCLK_M1_: C159.2 R282.2 U20.20 | length 1766.3
  TOP w5: v1(2530,1775) 2549.13,1794.13 U20.20@2562.48,1794.13 ; v1(3139,2770) 3148,2779 3148,2813 3205,2870 C159.2@3307.28,2870 3342,2835.28 R282.2@3342,2832.72
  BOTTOM w5: v1(2530,1775) 2540,1785 2877,1785 2935,1843 2935,1890 3045,2000 3045,2400 3065,2420 3065,2555 3109,2599 3109,2699 3125,2715 3125,2756 v1(3139,2770)
GMAC1_TXD0_M1: J2.47 R272.1 | length 116
  TOP w5: J2.47@3231.89,2706.42 3231.89,2736.89 3240,2745 3240,2785 3252.28,2797.28 R272.1@3269,2797.28
GMAC1_TXD0_M1_: R272.2 U20.18 | length 1659.9
  TOP w5: v1(2532.37,1819) 2539,1825.63 U20.18@2562.48,1825.63 ; v1(3244.64,2817.36) 3260,2832.72 R272.2@3269,2832.72
  BOTTOM w5: v1(2532.37,1819) 2554,1819 2570,1835 2775,1835 2784,1844 2807,1844 2833,1818 2864,1818 2904,1858 2904,1904 2956,1956 2956,2005.61 3015,2064.61 3015,2535.61 3088.39,2609 3088.39,2708.39 3105,2725 3105,2800 3120,2815 3168,2815 3186,2797 3202,2797 3222.36,2817.36 v1(3244.64,2817.36)
GMAC1_TXD1_M1: J2.49 R275.1 | length 103.2
  TOP w5: J2.49@3212.2,2706.42 3212.2,2737.2 3230,2755 3230,2785.28 R275.1@3218,2797.28
GMAC1_TXD1_M1_: R275.2 U20.17 | length 1625.7
  TOP w5: v1(2516,1840.5) 2518,1838.5 2547.12,1838.5 2550,1841.38 U20.17@2562.48,1841.38 ; v1(3193,2816) 3209.72,2832.72 R275.2@3218,2832.72
  BOTTOM w5: v1(2516,1840.5) 2518.5,1838 2558,1838 2565,1845 2770,1845 2780,1855 2811,1855 2837,1829 2857,1829 2892,1864 2892,1907 2946,1961 2946,2010 3005,2069 3005,2540 3077.79,2612.79 3077.79,2712.79 3095,2730 3095,2805 3116,2826 3183,2826 v1(3193,2816)
GMAC1_TXD2_M1: J2.35 R276.1 | length 146.7
  TOP w5: J2.35@3350,2706.42 3350,2739 3376,2765 3407.72,2765 R276.1@3440,2797.28
GMAC1_TXD2_M1_: R276.2 U20.16 | length 1786
  TOP w5: v1(2537.87,1857.13) U20.16@2562.48,1857.13 ; v1(3417,2835) 3419.28,2832.72 R276.2@3440,2832.72
  BOTTOM w5: v1(2537.87,1857.13) 2617.13,1857.13 2645,1885 2671,1885 2689,1867 2862,1867 2882,1887 2882,1913 2935,1966 2935,2014 2995,2074 2995,2546.82 3067.18,2619 3067.18,2717.18 3085,2735 3085,2810 3111,2836 3334,2836 3354,2816 3377,2816 3396,2835 v1(3417,2835)
GMAC1_TXD3_M1: J2.37 R279.1 | length 116.6
  TOP w5: J2.37@3330.31,2706.42 3330.31,2739.31 3388.28,2797.28 R279.1@3390,2797.28
GMAC1_TXD3_M1_: R279.2 U20.15 | length 1758.9
  TOP w5: v1(2519,1876) 2546,1876 2549.13,1872.87 U20.15@2562.48,1872.87 ; v1(3369,2835) 3371.28,2832.72 R279.2@3390,2832.72
  BOTTOM w5: v1(2519,1876) 2621,1876 2640,1895 2677,1895 2694,1878 2858,1878 2872,1892 2872,1918 2925,1971 2925,2019 2985,2079 2985,2552 3057,2624 3057,2722 3075,2740 3075,2815 3106,2846 3358,2846 v1(3369,2835)
GMAC1_TXEN_M1: J2.32 R280.1 | length 124.3
  TOP w5: J2.32@3379.52,2383.58 3379.52,2288.2 R280.1@3400,2267.72
GMAC1_TXEN_M1_: R280.2 U20.19 | length 2076.2
  TOP w5: v1(2404,1706) 2425,1727 2425,1769 2436,1780 2455,1780 2490,1815 2510,1815 2525,1800 2540,1800 2549.88,1809.88 U20.19@2562.48,1809.88 ; v1(3376,2245) 3388.72,2232.28 R280.2@3400,2232.28
  BOTTOM w5: v1(2404,1706) 2404,1683 2370,1649 2370,1535 2400,1505 2530,1505 2560,1475 2900.06,1475 2958.33,1533.26 2958.33,1540.04 3001,1582.71 3001,1648.86 3030.14,1678 3068,1678 3120,1730 3120,1765 3205,1850 3205,2209 3236,2240 3371,2240 v1(3376,2245)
